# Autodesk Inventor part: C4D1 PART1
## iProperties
Shininess: 64.0
Length Units: 11272
Angle Units: 11279
Time Units: 11290
Mass Units: 11283
Length Display Precision: 3
Angle Display Precision: 2
Compacted: True
Part Number: C4D1 PART1
Document SubType Name: Modeling
Created: 2003-01
Designer: Owner
Density: 1 g/cm^3
Density: 0.0
Volumn: 0.0
Area: 0.0
PropertySet Name: Model Information
Control State: 0
Master: False
Checked Out: False
Author: Owner
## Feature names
1. ExtrusionBlind1
2. ExtrusionBlind2
3. ExtrusionBlind3
4. ExtrusionBlind4
5. ExtrusionThru1
6. Hole1
